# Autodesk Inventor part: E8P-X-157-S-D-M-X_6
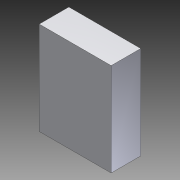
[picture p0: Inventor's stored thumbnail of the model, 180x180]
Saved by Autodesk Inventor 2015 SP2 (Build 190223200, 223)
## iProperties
Created: 2012-07
Part Number: E8P-X-157-S-D-M-X_6
Material: Allgemein
Document SubType Name: Modeling
Designer: rYan
Density: 1 g/cm^3
Mass: 0.0277898 g
Surface Area: 0.805932 cm^2
Volume: 0.0277898 cm^3
Appearance: Vorgabe
Author: rYan
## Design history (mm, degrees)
node "E8P-X-157-S-D-M-X_61"
node "E8P-X-157-S-D-M-X_6"
node "Basis1"
